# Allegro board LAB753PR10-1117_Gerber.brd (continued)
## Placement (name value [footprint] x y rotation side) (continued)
PR208  0_0402_5%  [R_0402]  150.92 24.98 90 top
PR209  0_0402_5%  [R_0402]  148.25 24.99 90 top
PR210  100K_0402_5%  [R_0402]  152.71 24.98 90 top
PR300  0_0402_5%  [R_0402]  239.88 26.25 0 bottom
PR301  100K_0402_5%  [R_0402]  243.02 24.86 180 bottom
PR302  2.2_0603_5%  [R_0603]  245.87 24.73 0 bottom
PR303  137K_0402_1%  [R_0402]  239.88 24.39 0 bottom
PR304  0_0402_5%  [R_0402]  239.88 25.36 0 bottom
PR305  4.7_1206_5%  [R_1206]  256.99 24.86 90 bottom
PR306  470K_0402_1%  [R_0402]  242.39 30.06 180 bottom
PR307  5.23K_0402_1%  [R_0402]  240.79 29.05 180 bottom
PR308  10K_0402_1%  [R_0402]  240.79 28.16 180 bottom
PR309  2.2_0603_5%  [R_0603]  133.94 106.91 0 bottom
PR310  10K_0402_1%  [R_0402]  130.34 110.94 180 bottom
PR311  470K_0402_1%  [R_0402]  131.76 112.49 90 bottom
PR312  137K_0402_1%  [R_0402]  129.43 107.22 0 bottom
PR313  20K_0402_1%  [R_0402]  129.4 109.06 0 bottom
PR314  4.7_1206_5%  [R_1206]  143.32 108.04 0 top
PR315  0_0402_5%  [R_0402]  129.4 108.17 0 bottom
PR316  9.31K_0402_1%  [R_0402]  129.44 111.86 90 bottom
PR317  0_0402_1%  [R_0402]  157.91 117.88 0 bottom
PR318  100K_0402_5%  [R_0402]  132.72 106.9 180 bottom
PR319  100_0402_1%  [R_0402]  130.35 112.78 270 bottom
PR403  1M_0402_1%  [R_0402]  142.83 85.1 180 bottom
PR405  4.99K_0402_1%  [R_0402]  204.97 23.87 270 top
PR406  5.62K_0402_1%  [R_0402]  203.68 22.47 270 top
PR407  12K_0402_1%  [R_0402]  204.79 18.07 270 top
PR500  130_0402_1%~D  [R_0402]  135.59 130.37 45 top
PR501  0_0402_5%  [R_0402]  102.68 119.46 90 top
PR502  2.2_0603_5%  [R_0603]  101.54 116.04 270 top
PR503  75_0402_5%  [R_0402]  136.1 132.41 315 bottom
PR504  54.9_0402_1%  [R_0402]  138.17 130.23 135 top
PR505  0_0402_5%  [R_0402]  135.6 131.66 225 top
PR506  0_0402_5%  [R_0402]  135.42 131.73 315 bottom
PR507  21K_0402_1%  [R_0402]  133.55 129.87 315 bottom
PR508  0_0402_5%  [R_0402]  138.18 131.52 315 top
PR509  3.24K_0402_1%  [R_0402]  134.17 130.49 315 bottom
PR510  10K_0603_1%  [R_0603]  141.23 119.99 225 top
PR511  0_0402_5%  [R_0402]  139.3 131.34 225 bottom
PR512  21K_0402_1%  [R_0402]  134.78 131.11 315 bottom
PR513  4.7_1206_5%  [R_1206]  110.37 120.99 0 top
PR514  3.65K_0603_1%  [R_0603]  140.38 120.84 225 top
PR515  10_0402_1%  [R_0402]  139.26 120 315 bottom
PR516  10K_0402_1%  [R_0402]  143.53 123.1 315 bottom
PR518  10K_0402_1%  [R_0402]  142.95 124.99 135 bottom
PR519  1.91K_0402_1%  [R_0402]  139.26 130.08 45 bottom
PR520  0_0402_5%  [R_0402]  132.02 124.68 225 bottom
PR521  90.9K_0402_1%  [R_0402]  140.57 129.11 45 top
PR522  0_0402_5%  [R_0402]  140.54 130.1 225 bottom
PR523  0_0402_5%~D  [R_0402]  132.46 123.78 45 bottom
PR524  0_0402_5%  [R_0402]  141.17 128.23 135 bottom
PR525  3.83K_0402_1%  [R_0402]  143.09 132.25 180 bottom
PR526  0_0402_5%  [R_0402]  136.15 120.05 225 bottom
PR527  0_0402_5%  [R_0402]  141.73 131.22 315 bottom
PR528  27.4K_0402_1%  [R_0402]  142.45 133.12 180 bottom
PR529  6.04K_0402_1%  [R_0402]  137.6 128.11 315 top
PR530  1_0603_1%~D  [R_0603]  136.31 118.49 315 bottom
PR533  499_0402_1%  [R_0402]  141.56 127.09 180 top
PR534  2.2_0603_5%  [R_0603]  132.1 129.66 315 bottom
PR535  590_0402_1%  [R_0402]  139.89 121.87 315 bottom
PR536  3.65K_0603_1%  [R_0603]  144.46 123.32 0 top
PR537  2.87K_0402_1%  [R_0402]  142.45 125.27 180 top
PR538  10K_0603_1%  [R_0603]  145.86 124.56 180 top
PR539  909_0402_1%  [R_0402]  146.34 124.32 90 bottom
PR541  4.7_1206_5%  [R_1206]  118.43 121.19 0 top
PR543  2K_0402_1%  [R_0402]  139.12 126.32 315 top
PR544  10_0402_1%  [R_0402]  143.58 124.35 225 bottom
PR545  1.5K_0402_1%  [R_0402]  139.93 120.59 135 bottom
PR546  10K_0402_1%  [R_0402]  144.79 123.07 135 bottom
PR547  10K_0402_1%  [R_0402]  141.15 119.35 135 bottom
PR548  0_0402_5%  [R_0402]  142.36 121.76 315 bottom
PR549  11K_0402_1%  [R_0402]  137.22 124.35 315 top
PR550  2.2_0603_5%  [R_0603]  134.07 121.22 45 bottom
PR551  2.61K_0402_1%  [R_0402]  140.66 121.88 135 top
PR552  3.65K_0603_1%  [R_0603]  143.39 123.92 270 top
PR553  10K_0603_1%  [R_0603]  142.31 123.66 180 top
PR554  4.7_1206_5%  [R_1206]  127.51 120.61 0 top
PR555  10K_0402_1%  [R_0402]  144.81 124.31 135 bottom
PR556  10_0402_1%  [R_0402]  142.98 122.41 135 bottom
PR557  10K_0402_1%  [R_0402]  141.76 120 135 bottom
PR558  5.1M_0402_5%  [R_0402]  138.08 119.98 135 bottom
PR600  0_0402_5%~D  [R_0402]  174.84 24.47 270 top
PR601  2.2 +-5% 0603  [R_0603]  177.71 29.78 90 top
PR602  0_0402_5%~D  [R_0402]  175.71 23.57 0 top
PR603  0.005_1206_LE_1%  [PS0612FKM070R005Z_1206-LE]  157.58 47.99 180 top
PR604  0.005_1206_LE_1%  [PS0612FKM070R005Z_1206-LE]  169.04 43.18 90 top
PR606  39.2K_0402_1%  [R_0402]  180.28 21.95 270 top
PR607  0_0402_5%  [R_0402]  176.52 26.33 180 top
PR608  4.7_1206_5%  [R_1206]  175.32 45.09 0 top
PR610  0_0402_5%  [R_0402]  176.52 25.44 180 top
PR611  1.5K_0402_1%  [R_0402]  177.55 21.95 270 top
PR613  39.2K_0402_1%  [R_0402]  179.36 21.03 90 top
PR614  10K_0402_1%~D  [R_0402]  175.62 29.21 0 top
PR615  0_0402_5%  [R_0402]  176.53 28.32 180 top
PR616  30.1K_0402_1%  [R_0402]  174.78 21.71 0 top
PR617  2.2 +-5% 0603  [R_0603]  184.82 29.78 90 top
PR618  1.5K_0402_1%  [R_0402]  174.78 22.67 0 top
PR619  0_0402_5%  [R_0402]  184.63 26.26 0 top
PR620  0_0402_5%~D  [R_0402]  182.58 19.05 180 top
PR621  0_0402_5%  [R_0402]  176.53 30.19 180 top
PR622  0_0402_5%  [R_0402]  186.36 20.8 180 top
PR623  3K_0402_1%  [R_0402]  177.52 20.12 0 top
PR624  100_0402_1%  [R_0402]  183 21.03 90 top
PR625  2.2 +-5% 0603  [R_0603]  182.37 29.86 90 top
PR626  4.7_1206_5%  [R_1206]  183.53 45.09 0 top
PR627  0_0402_5%  [R_0402]  186.36 21.71 180 top
PR629  100_0402_1%  [R_0402]  185.54 22.6 180 top
PR631  10K_0402_1%~D  [R_0402]  181.66 18.15 0 top
PR633  2.2 +-5% 0603  [R_0603]  188.34 27.33 180 top
PR638  10K_0402_1%  [R_0402]  185.54 23.59 180 top
PR639  10K_0402_1%~D  [R_0402]  185.55 27.15 180 top
PR640  4.7_1206_5%  [R_1206]  190.69 45.03 0 top
PR641  0_0402_5%  [R_0402]  188.76 31.3 180 top
PR642  0_0402_5%  [R_0402]  190.5 27.71 0 top
PR643  2.2 +-5% 0603  [R_0603]  193.8 31.46 180 top
PR646  10K_0402_1%  [R_0402]  185.54 24.47 180 top
PR648  10K_0402_1%  [R_0402]  185.54 25.36 180 top
PR649  10K_0402_1%  [R_0402]  180.03 31.21 270 top
PR650  510K_0402_1%  [R_0402]  182.06 21.95 270 top
PR674  4.7_1206_5%  [R_1206]  145.05 88.27 270 bottom
PR677  200K_0402_5%  [R_0402]  141.91 84.15 0 bottom
PR681  30.1K_0402_1%  [R_0402]  140.36 85.1 180 bottom
PR685  38.3K_0402_1%  [R_0402]  139.45 86.03 0 bottom
PR700  1M_0402_5%  [R_0402]  32.88 39.66 180 top
PR701  3M_0402_5%  [R_0402]  31.98 40.6 0 top
PR702  0.004_1206_1%  [R_1206_4P-D]  45 22.95 0 top
PR703  0_0402_5%  [R_0402]  41.47 29.67 90 top
PR704  0_0402_5%  [R_0402]  42.36 29.67 90 top
PR705  4.12K_0603_1%  [R_0603]  35.16 39.31 0 top
PR706  4.12K_0603_1%  [R_0603]  35.15 40.6 0 top
PR707  10_1206_1%  [R_1206]  35.5 37.87 270 top
PR708  2.2_0603_1%  [R_0603]  43.36 42.94 270 top
PR709  20K_0402_1%  [R_0402]  46.23 39.09 0 top
PR710  6.65K_0402_1%  [R_0402]  48.05 39.1 90 top
PR711  2.7K_0402_1%  [R_0402]  46.23 39.99 0 top
PR712  0.01_1206_1%  [R_1206_4P-D]  62.71 45.94 0 bottom
PR713  4.7_1206_5%  [R_1206]  51.69 41.94 270 top
PR714  100K_0402_5%  [R_0402]  37.49 38.21 0 top
PR715  120K_0402_5%  [R_0402]  38.4 37.32 180 top
PR716  324K_0402_1%  [R_0402]  37.49 36.45 0 top
PR717  0_0402_5%  [R_0402]  39.36 34.89 270 top
PR718  10K_0402_5%  [R_0402]  46.33 35.7 0 top
PR719  49.9K_0402_1%  [R_0402]  37.51 35.59 270 top
PR720  0_0402_5%  [R_0402]  43.1 32.87 90 top
PR721  0_0402_5%  [R_0402]  43.99 32.88 90 top
PR722  10_0402_5%  [R_0402]  47.61 38.15 0 top
PR723  10_0402_5%  [R_0402]  47.61 37.26 0 top
PR724  0_0402_5%  [R_0402]  42.21 32.87 90 top
PR725  4.7_0402_5%  [R_0402]  38.81 17.2 180 bottom
PR726  4.7_0402_5%  [R_0402]  38.81 16.31 180 bottom
PR727  0_0402_5%  [R_0402]  47.25 34.76 180 top
PR729  1M_0402_1%  [R_0402]  65.13 49 0 top
PR730  1M_0402_1%  [R_0402]  66.04 49.98 180 top
PR731  200K_0402_1%  [R_0402]  59.73 49.16 90 top
PR732  3.3K_0402_1%  [R_0402]  59.73 48.19 0 top
PU100  -  [TPS51285BRUKR_QFN20_3X3]  21.95 29.83 270 top
PU200  -  [RT8207MZQW_WQFN20_3X3]  149.34 29.78 270 top
PU300  -  [TPS51212DSCR_SON10_3X3]  242.51 26.51 90 bottom
PU301  -  [TPS51212DSCR_SON10_3X3]  131.97 108.87 90 bottom
PU401  -  [RT9041E-15GQW_WDFN8_2X2]  206.3 21.68 180 top
PU500  ISL95812HRZ-T_QFN32_4x4  [ISL95812HRZ-T_QFN32_4X4]  137.9 128.85 315 bottom
PU501  -  [ISL6208BCRZ-T_QFN8_2X2]  102.88 115.96 0 top
PU600  -  [RT8813AGQW_WQFN24_4X4]  178.77 27.3 270 top
PU601  RT9610BZQW WDFN8 MOSFET DRIVER ET88  [ISL6208BCRZ-T_QFN8_2X2]  188.96 30.18 270 top
PU602  SY8036LDBC_DFN10_3X3  [SY8036DBC_DFN10_3X3]  143.03 89.55 270 bottom
PU700  -  [BQ24780RUYR_WQFN28_4X4]  40.82 38.59 0 top
Q28  -  [DMN66D0LDW-7_SOT363-6]  139.72 15.38 180 top
Q29  -  [DMN66D0LDW-7_SOT363-6]  142.83 11.58 180 top
Q30  -  [DMN66D0LDW-7_SOT363-6]  136.35 15.38 180 top
Q31  -  [DMN66D0LDW-7_SOT363-6]  138.45 11.58 180 top
Q32  -  [DMN66D0LDW-7_SOT363-6]  132.99 15.43 180 top
Q33  -  [DMN66D0LDW-7_SOT363-6]  124.99 11.45 180 top
Q34  -  [DMN66D0LDW-7_SOT363-6]  129.62 15.26 180 top
Q35  -  [DMN66D0LDW-7_SOT363-6]  121.62 11.45 180 top
Q36  -  [DMN66D0LDW-7_SOT363-6]  126.26 15.26 180 top
Q37  -  [DMN66D0LDW-7_SOT363-6]  118.25 11.45 180 top
Q38  -  [DMN66D0LDW-7_SOT363-6]  122.89 15.26 180 top
Q39  -  [DMN66D0LDW-7_SOT363-6]  114.89 11.45 180 top
Q40  -  [2N7002K_SOT23-3]  311.49 39.84 90 top
Q41  -  [2N7002K_SOT23-3]  144.44 24.69 270 top
Q2407  -  [MMST3904-7-F_SOT323-3]  132.69 116.64 90 top
Q2408  -  [MMST3904-7-F_SOT323-3]  202.35 52.39 315 bottom
Q2409  SI3456DDV-T1-GE3_TSOP6~D  [SI3456DDV-T1-GE3_TSOP6]  213.42 123.14 180 bottom
Q2410  SSM3K7002FU_SC70-3~D  [SSM3K7002FU_SC70-3]  213.28 121.01 90 bottom
Q2411  -  [DMN66D0LDW-7_SOT363-6]  89.08 12.41 0 top
Q2412  -  [DMN66D0LDW-7_SOT363-6]  79.81 12.41 0 top
Q2413  -  [DMN66D0LDW-7_SOT363-6]  82.22 12.41 0 top
QA2  SSM3K7002FU_SC70-3~D  [SSM3K7002FU_SC70-3]  14.2 14.07 270 bottom
QA3  -  [SSM3K7002FU_SC70-3]  14.2 16.5 270 bottom
QA7  -  [DMN66D0LDW-7_SOT363-6]  4.57 7.82 90 top
QA11  -  [AO3413_SOT23-3]  27.07 9.46 0 bottom
QA12  -  [AO3413_SOT23-3]  17.74 11.41 90 bottom
QA13  -  [AO3413_SOT23-3]  23.1 8.93 0 bottom
QA14  -  [DMN66D0LDW-7_SOT363-6]  9.69 15.36 0 bottom
QC1  LBSS138LT1G_SOT-23-3  [LBSS138LT1G_SOT23-3]  120.87 109.88 90 top
QE1  SSM3K7002F_SC59-3~D  [SSM3K7002F_SC59-3]  262.69 20.11 135 bottom
QE3  SSM3K7002F_SC59-3~D  [SSM3K7002F_SC59-3]  276.08 19.99 225 bottom
QE4  SSM3K7002F_SC59-3~D  [SSM3K7002F_SC59-3]  268.71 19.29 225 bottom
QE6  SSM3K7002F_SC59-3~D  [SSM3K7002F_SC59-3]  273.35 17.32 225 bottom
QE7  SSM3K7002F_SC59-3~D  [SSM3K7002F_SC59-3]  266.97 17.71 135 bottom
QE8  LP2301ALT1G 1P SOT-23-3  [SI2301CDS-T1-GE3_SOT23-3]  283.3 7.96 270 bottom
QE9  -  [SSM3K7002F_SC59-3]  287.9 8.22 90 bottom
QE10  -  [SSM3K7002F_SC59-3]  172.2 134.56 270 bottom
QE12  DMN66D0LDW-7_SOT363-6~D  [DMN66D0LDW-7_SOT363-6]  166.94 136.39 270 bottom
QE13  DMN66D0LDW-7_SOT363-6~D  [DMN66D0LDW-7_SOT363-6]  163.2 137.49 90 bottom
QE14  SSM3K7002F_SC59-3~D  [SSM3K7002F_SC59-3]  156.76 130.12 180 top
QE16  -  [DMN66D0LDW-7_SOT363-6]  224.04 111.57 90 top
QF2  -  [MMBT3904WT1G_SC70-3]  217.17 123 0 bottom
QH1  SSM3K7002FU_SC70-3~D  [SSM3K7002FU_SC70-3]  234.25 35.47 90 bottom
QH3  DMN66D0LDW-7  [DMN66D0LDW-7_SOT363-6]  231.09 20.66 180 top
QH4  -  [DMN66D0LDW-7_SOT363-6]  225.92 18.79 0 top
QL3  2N7002_SOT23  [2N7002_SOT23-3]  321.25 71.81 180 top
QM1  LP2301ALT1G 1P SOT-23-3  [SI2301CDS-T1-GE3_SOT23-3]  291.91 32.15 0 top
QM2  -  [DMN66D0LDW-7_SOT363-6]  294.22 27.46 90 top
QM3  LP2301ALT1G 1P SOT-23-3  [SI2301CDS-T1-GE3_SOT23-3]  296.17 32.13 0 top
QN2  DII-DMN65D8LW-7~D  [SSM3K7002FU_SC70-3]  174.44 18.95 270 top
QN3  SSM3K7002FU_SC70-3~D  [SSM3K7002FU_SC70-3]  151.41 15.13 180 bottom
QN4  -  [2N7002K_SOT23-3]  165.62 33.36 270 top
QN5  -  [2N7002K_SOT23-3]  165.62 29.32 270 top
QV1  -  [SI3457CDV-T1-GE3_TSOP6]  82.9 117.24 315 top
QV2  -  [2N7002KW_SOT323-3]  81.69 113.4 180 top
QV12  2N7002H 1N_SOT23-3  [2N7002_SOT23-3]  140.92 77.54 90 bottom
QV13  2N7002DW-T/R7_SOT363-6  [2N7002DW-T-R7_SOT363-6]  162.75 53.2 270 top
QV21  2N7002W-T/R7_SOT323-3  [2N7002W-T-R7_SOT323-3]  213.3 104 180 bottom
QV23  2N7002W-T/R7_SOT323-3  [2N7002W-T-R7_SOT323-3]  157.04 128.04 270 top
QV24  2N7002W-T/R7_SOT323-3  [2N7002W-T-R7_SOT323-3]  198.88 132.67 270 top
QV25  2N7002W-T/R7_SOT323-3  [2N7002W-T-R7_SOT323-3]  215.08 65.41 0 bottom
QV89  2N7002DW-T/R7_SOT363-6  [2N7002DW-T-R7_SOT363-6]  159.75 53.81 0 bottom
QV91  2N7002DW-T/R7_SOT363-6  [2N7002DW-T-R7_SOT363-6]  149.63 57.89 0 top
R1  0_0402_5%  [R0402_0OHM]  92.65 64.87 270 top
R2  56_0402_5%  [R_0402]  87.94 101.88 0 bottom
R3  100_0402_1%  [R_0402]  91.44 108.75 270 top
R144  39K_0402_5%  [R_0402]  137.42 14.43 90 top
R145  39K_0402_5%  [R_0402]  127.32 14.43 90 top
R146  100K_0402_5%  [R_0402]  137.42 13.57 270 top
R147  100K_0402_5%  [R_0402]  127.32 13.57 270 top
R148  100K_0402_5%  [R_0402]  87.05 13.81 0 top
R149  39K_0402_5%  [R_0402]  87.05 12.92 0 top
R150  39K_0402_5%  [R_0402]  140.46 10.87 90 top
R151  39K_0402_5%  [R_0402]  119.32 10.87 90 top
R152  100K_0402_5%  [R_0402]  77.84 13.74 0 top
R153  39K_0402_5%  [R_0402]  77.84 12.85 0 top
R154  100K_0402_5%  [R_0402]  140.46 10.01 270 top
R155  100K_0402_5%  [R_0402]  119.32 10.01 270 top
R156  39K_0402_5%  [R_0402]  130.69 14.43 90 top
R157  39K_0402_5%  [R_0402]  123.95 14.43 90 top
R158  100K_0402_5%  [R_0402]  134.01 13.59 270 top
R159  100K_0402_5%  [R_0402]  123.95 13.57 270 top
R160  39K_0402_5%  [R_0402]  139.51 10.87 90 top
R161  39K_0402_5%  [R_0402]  115.95 10.87 90 top
R162  100K_0402_5%  [R_0402]  139.51 10.01 270 top
R163  100K_0402_5%  [R_0402]  115.95 10.01 270 top
R164  39K_0402_5%  [R_0402]  134.03 14.48 90 top
R165  39K_0402_5%  [R_0402]  120.59 14.43 90 top
R166  100K_0402_5%  [R_0402]  130.69 13.57 270 top
R167  100K_0402_5%  [R_0402]  120.59 13.57 270 top
R168  39K_0402_5%  [R_0402]  122.68 10.87 90 top
R169  39K_0402_5%  [R_0402]  112.59 10.75 90 top
R170  100K_0402_5%  [R_0402]  122.68 10.01 270 top
R171  100K_0402_5%  [R_0402]  112.59 9.88 270 top
R172  100K_0402_5%  [R_0402]  85.42 13.81 180 top
R173  39K_0402_5%  [R_0402]  85.42 12.92 180 top
R174  10K_0402_5%  [R_0402]  50.08 15.74 270 bottom
R175  100K_0402_5%  [R_0402]  313.25 39.38 90 top
R176  100K_0402_5%  [R_0402]  307.6 40.3 270 top
R177  22_0603_5%  [R_0603]  142.24 23.08 0 top
R178  0_0402_5%  [R0402_0OHM]  229.07 21.22 90 bottom
R179  300K_0402_5%~D  [R_0402]  212.17 119.92 180 bottom
R180  1.5M_0402_5%~D  [R_0402]  212.17 120.82 180 bottom
R181  10K_0402_5%  [R_0402]  140.46 10.58 90 bottom
R182  0_0402_5%  [R0402_0OHM]  50.98 15.74 270 bottom
RA40  33_0402_5%~D  [R_0402]  20.16 21.76 270 top
RA41  10K_0402_5%  [R_0402]  3.81 15.6 0 bottom
RA42  20K_0402_1%~D  [R_0402]  18.46 7.58 90 top
RA43  10K_0402_5%~D  [R_0402]  14.54 13.18 270 bottom
RA44  10K_0402_5%~D  [R_0402]  4.73 13.77 90 bottom
RA46  39.2K_0402_1%  [R_0402]  24.35 10.68 0 top
RA47  20K_0402_1%~D  [R_0402]  26.04 12.49 180 top
RA48  10K_0402_1%~D  [R_0402]  24.35 11.58 0 top
RA49  5.11K_0402_1%~D  [R_0402]  26.04 13.38 180 top
RA50  0_0402_5%~D  [R_0402]  6.05 12.24 90 bottom
RA51  0_0402_5%  [R0402_0OHM]  21.5 22.65 270 top
RA53  0_0402_5%~D  [R_0402]  10.42 33.75 225 bottom
RA54  0_0402_5%~D  [R_0402]  1.65 16.32 90 bottom
RA55  0_0805_5%~D  [R_0805]  13.73 20.02 270 bottom
RA57  0_0805_5%~D  [R_0805]  17.63 14.23 180 bottom
RA64  10K_0402_1%~D  [R_0402]  19.34 7.58 90 top
RA80  10K_0402_5%~D  [R_0402]  223.98 16.09 180 bottom
RA81  560_0402_5%  [R_0402]  225.74 15.19 90 bottom
RA84  560_0402_5%  [R_0402]  224.86 15.19 90 bottom
RA85  100K_0402_1%  [R_0402]  8.68 16.8 180 bottom
RA86  100K_0402_1%  [R_0402]  5.96 15.84 0 bottom
RA87  100K_0402_1%  [R_0402]  5.96 16.73 0 bottom
RA91  100K_0402_1%  [R_0402]  7.98 33.92 0 bottom
RA92  0_0402_5%  [R0402_0OHM]  17.97 7.81 90 bottom
RA93  0_0402_5%~D  [R_0402]  6.65 8.27 180 top
RA94  0_0402_5%~D  [R_0402]  6.63 9.18 180 top
RA95  0_0603_5%  [R0603_0OHM]  27.07 11.47 0 bottom
RA96  0_0402_5%  [R_0402]  24.01 20.11 90 top
RA100  2.2K_0402_5%  [R_0402]  16.04 11 270 bottom
RA101  10K_0804_8P4R_5%~D  [RP_0804_8P4R]  22.45 6.16 180 top
RA102  2.2K_0402_5%  [R_0402]  28.41 8.69 270 top
RA105  24.9K_0402_1%  [R_0402]  14.99 8.27 90 bottom
RA106  24.9K_0402_1%  [R_0402]  29.48 9.37 270 bottom
RA107  100_0402_1%  [R_0402]  6.54 8.87 270 bottom
RA108  100_0402_1%  [R_0402]  14.1 8.27 90 bottom
RA109  10_0603_5%  [R_0603]  10 20.77 270 bottom
RA111  5.6K_0402_1%  [R_0402]  8.89 34.86 180 bottom
RA112  10K_0402_1%  [R_0402]  6.02 33.92 0 bottom
RA113  10K_0402_1%  [R_0402]  6.85 32.66 225 bottom
RA114  10K_0402_1%  [R_0402]  8.66 12.5 0 bottom
RA115  10K_0402_1%  [R_0402]  8.65 14.86 270 bottom
RA116  5.9K_0402_5%  [R_0402]  5.09 33.77 180 bottom
RA117  5.9K_0402_5%  [R_0402]  9.97 31.65 270 bottom
RA118  13.3K_0402_1%  [R_0402]  12.7 8.21 90 top
RA119  13.3K_0402_1%  [R_0402]  9.39 6.5 180 top
RA120  10K_0402_1%  [R_0402]  14.49 8.22 180 top
RA122  10K_0402_1%  [R_0402]  6.64 6.5 0 top
RA123  470K_0402_5%  [R_0402]  5.78 6.54 180 top
RA126  2.2K_0402_5%  [R_0402]  2.62 12.28 180 bottom
RA127  5.1K_0402_1%  [R_0402]  24.56 16.23 180 bottom
RA128  12K_0402_1%  [R_0402]  28.12 16.35 0 bottom
RA129  10K_0402_5%  [R_0402]  25.48 17.13 180 bottom
RA130  10_0402_1%  [R_0402]  4.66 16.47 90 bottom
RA131  10_0402_1%  [R_0402]  3.71 16.47 90 bottom
RA132  10_0402_1%  [R_0402]  1.72 18.2 90 bottom
RA133  10_0402_1%  [R_0402]  2.59 18.2 90 bottom
RA137  66.5K_0402_1%  [R_0402]  6.05 14.92 270 bottom
RA138  10K_0402_1%  [R_0402]  4.22 6.23 180 bottom
RA139  100K_0402_5%  [R_0402]  4.13 31.88 270 bottom
RA140  100K_0402_5%  [R_0402]  9.89 29.32 225 bottom
RC1  24.9_0402_1%  [R_0402]  132.79 83.84 180 top
RC11  62_0402_5%  [R_0402]  88.85 102.77 180 bottom
RC12  470_0402_5%  [R_0402]  92.65 63.1 270 top
RC17  0_0402_5%  [R0402_0OHM]  88.85 100.29 180 bottom
RC18  10K_0402_5%  [R_0402]  89.46 96.8 0 top
RC21  100_0402_1%  [R_0402]  96.71 64.87 270 top
RC22  75_0402_1%  [R_0402]  94.43 64.87 270 top
RC23  100_0402_1%  [R_0402]  95.57 64.87 270 top
RC24  100K_0402_5%  [R_0402]  82.67 64.92 0 top
RC26  1.8K_0402_1%  [R_0402]  89.85 62.18 90 top
RC27  1K_0402_5%  [R_0402]  87.94 99.4 0 bottom
RC30  3.3K_0402_1%  [R_0402]  90.74 63.1 270 top
RC31  0_0402_5%  [R0402_0OHM]  88.66 63.58 270 top
RC32  24.9_0402_1%  [R_0402]  123.26 83.13 90 top
RC33  0_0402_5%  [R_0402]  122.75 108.34 90 top
RC34  10K_0402_5%  [R_0402]  122.75 110.18 90 top
RC35  100K_0402_5%  [R_0402]  117.05 109.6 270 top
RC36  1K_0402_1%  [R_0402]  91.26 85.24 180 top
RC37  1K_0402_1%  [R_0402]  90.35 87.91 0 top
RC38  49.9_0402_1%  [R_0402]  114.37 109.32 270 top
RC39  49.9_0402_1%  [R_0402]  90.29 92.8 0 top
RC40  49.9_0402_1%  [R_0402]  113.48 109.32 270 top
RC41  1K_0402_1%  [R_0402]  91.26 90.2 180 top
RC42  1K_0402_1%  [R_0402]  91.26 86.96 180 top
RC43  1K_0402_1%  [R_0402]  91.26 89.27 180 top
RC44  100_0402_1%  [R_0402]  94.11 107.83 90 top
RC45  0_0402_5%  [R0402_0OHM]  93.22 107.83 90 top
RC46  0_0402_5%  [R0402_0OHM]  92.33 107.83 90 top
RC47  75_0402_1%  [R_0402]  89.28 107.83 90 top
RC48  43_0402_5%  [R_0402]  88.39 108.75 270 top
RC49  130_0402_1%  [R_0402]  90.36 108.75 270 top
RC50  150_0402_1%  [R_0402]  116.14 108.41 90 top
RC51  0_0603_5%  [R_0603]  88.97 105.19 180 bottom
RC52  10K_0402_5%  [R_0402]  115.25 109.32 270 top
RC53  6.04K_0402_1%  [R_0402]  133.42 95.88 90 top
RC54  0_0603_5%  [R_0603]  123.89 108.36 90 top
RC55  2.67K_0402_1%  [R_0402]  132.47 96.8 270 top
RC56  0_0402_5%  [R_0402]  80.79 63.02 0 top
RC57  0_0402_5%  [R_0402]  80.8 64.92 0 top
RD1  1K_0402_1%  [R_0402]  121.87 45.37 180 bottom
RD2  2.2_0402_1%  [R_0402]  126.05 46.27 270 bottom
RD3  1K_0402_1%  [R_0402]  123.89 46.27 270 bottom
RD4  24.9_0402_1%  [R_0402]  124.97 48.68 270 bottom
RD5  1K_0402_1%  [R_0402]  84.77 43.7 90 bottom
RD6  2.2_0402_1%  [R_0402]  80.75 43.7 90 bottom
RD7  10K_0402_5%  [R_0402]  136.78 44.55 270 bottom
RD8  10K_0402_5%  [R_0402]  139.83 44.62 270 bottom
RD9  1K_0402_1%  [R_0402]  81.64 43.7 90 bottom
RD10  24.9_0402_1%  [R_0402]  81.64 41.86 90 bottom
RD11  1K_0402_1%  [R_0402]  76.44 24.41 0 top
RD12  2.2_0402_1%  [R_0402]  73.87 22.49 0 top
RD13  1K_0402_1%  [R_0402]  73.87 23.45 0 top
RD14  24.9_0402_1%  [R_0402]  74.78 20.58 180 top
RD15  10K_0402_5%  [R_0402]  141.47 27.78 0 top
RD16  10K_0402_5%  [R_0402]  140.74 25.08 90 top
RE1  4.7K_0402_5%  [R_0402]  259.37 22.62 45 bottom
RE2  4.7K_0402_5%  [R_0402]  260.04 21.94 45 bottom
RE3  0_0603_5%  [R0603_0OHM]  259.27 31.78 90 bottom
RE4  0_0603_5%  [R0603_0OHM]  265.38 38.49 315 bottom
RE5  0_0603_5%~D  [R_0603]  268.73 36.73 180 bottom
RE6  0_0603_5%  [R0603_0OHM]  255.89 38.66 270 top
RE7  1K_0402_1%~D  [R_0402]  268.99 34.49 225 bottom
RE8  10K_0402_5%  [R_0402]  272.39 20.69 135 bottom
RE9  15_0402_5%  [R_0402]  252.03 40.36 270 bottom
RE10  15_0402_5%  [R_0402]  256.15 31.52 0 bottom
RE11  15_0402_5%  [R_0402]  254.55 41.94 180 bottom
RE12  10K_0402_5%~D  [R_0402]  259.12 35.59 270 bottom
RE13  10K_0402_5%~D  [R_0402]  259.98 39.02 180 bottom
RE14  10K_0402_5%~D  [R_0402]  259.98 38.06 180 bottom
RE15  100K_0402_5%  [R_0402]  263.59 17.95 45 bottom
RE16  100K_0402_5%  [R_0402]  273.11 20.04 315 bottom
RE17  100K_0402_5%  [R_0402]  271.38 19.68 135 bottom
RE18  0_0603_5%  [R_0603]  261.96 37.4 0 top
RE19  0_0402_5%~D  [R_0402]  266.65 27.41 0 top
RE20  10K_0402_5%  [R_0402]  252.4 44.73 0 top
RE21  100K_0402_5%  [R_0402]  272.61 18.19 225 bottom
RE23  100K_0402_5%  [R_0402]  267.86 15.55 45 bottom
RE25  4.7K_0402_1%  [R_0402]  219.89 111.19 180 top
RE26  4.7K_0402_1%~D  [R_0402]  153.93 21.95 270 top
RE27  4.7K_0402_1%  [R_0402]  153.91 20.16 0 top
RE28  100K_0402_5%  [R_0402]  279.34 8.23 270 bottom
RE29  4.7K_0402_1%~D  [R_0402]  152.15 22.49 90 top
RE30  4.7K_0402_1%  [R_0402]  151.26 22.49 90 top
RE31  10K_0402_5%~D  [R_0402]  222.3 117.02 0 top
RE32  4.7K_0402_1%  [R_0402]  152.67 14.51 180 top
RE33  4.7K_0402_1%  [R_0402]  183.5 135.26 0 bottom
RE34  4.7K_0402_1%  [R_0402]  183.5 134.37 0 bottom
RE35  4.7K_0402_1%  [R_0402]  183.14 132.97 180 bottom
RE36  4.7K_0402_1%  [R_0402]  180.46 132.96 0 bottom
RE37  10K_0402_5%  [R_0402]  153.91 19.27 0 top
RE38  100K_0402_5%  [R_0402]  159.04 134.89 180 top
RE39  100K_0402_5%  [R_0402]  161.3 138.74 0 bottom
RE40  4.7K_0402_1%~D  [R_0402]  223.22 118.85 180 top
RE41  10K_0402_5%~D  [R_0402]  183.5 136.18 0 bottom
RE42  4.7K_0402_1%~D  [R_0402]  222.3 119.79 0 top
RE43  4.7K_0402_1%~D  [R_0402]  223.22 117.96 180 top
RE44  4.7K_0402_1%~D  [R_0402]  222.3 120.68 0 top
RE45  4.7K_0402_1%  [R_0402]  183.68 139.37 90 bottom
RE46  4.7K_0402_1%  [R_0402]  225.06 112.36 270 top
RE47  4.7K_0402_1%  [R_0402]  220.84 111.01 90 top
RE62  0_0402_5%  [R0402_0OHM]  215.53 12.14 180 top
RE63  100K_0402_5%  [R_0402]  158.87 139.4 0 top
RE64  100K_0402_1%  [R_0402]  273.5 9.76 270 top
RE66  27K_0402_1%  [R_0402]  274.45 8.84 90 top
RE68  47K_0402_5%  [R_0402]  270.79 25.24 0 top
RE70  10K_0402_5%  [R_0402]  289.24 9.63 270 top
RE72  10K_0402_5%  [R_0402]  296.05 25.49 180 top
RE74  43_0402_1%  [R_0402]  293.63 19.17 180 top
RE75  10K_0402_5%  [R_0402]  276.99 29.54 90 top
RE76  43_0402_1%  [R_0402]  292.71 21.77 0 top
RE77  10K_0402_5%  [R_0402]  279.36 7.83 90 top
RE78  0_0402_5%  [R0402_0OHM]  296.01 21.77 0 top
RE79  10K_0402_5%  [R_0402]  293.19 10.56 90 top
RE80  10K_0402_5%  [R_0402]  276.99 14.63 180 bottom
RE81  1K_0402_5%  [R_0402]  292.25 13.96 270 top
RE82  100K_0402_5%  [R_0402]  295.01 15.09 90 top
RE83  10K_0402_5%  [R_0402]  289.5 29.86 90 top
RE85  53.6K_0402_5%  [R_0402]  296.9 13.06 90 top
RE89  0_0402_5%  [R_0402]  284.8 30.77 270 top
RE90  2.2K_0804_8P4R_5%  [RP_0804_8P4R]  282.01 9.18 270 top
RE91  47K_0402_5%  [R_0402]  239.99 40.46 90 top
RE92  10K_0402_5%  [R_0402]  288.47 29.85 90 top
RE93  4.7K_0402_5%  [R_0402]  282.07 30.39 270 top
RE94  4.7K_0402_5%  [R_0402]  281.18 30.39 270 top
RE98  0_0402_5%  [R_0402]  243.65 46.84 270 top
RE99  100K_0402_5%  [R_0402]  239.77 37.47 0 bottom
RE100  4.7K_0402_5%  [R_0402]  185.79 131.5 90 bottom
RE101  4.7K_0402_5%  [R_0402]  186.7 131.5 90 bottom
RE102  100K_0402_5%  [R_0402]  236.45 45.53 180 top
RF1  10K_0402_5%  [R_0402]  67.73 59.23 270 bottom
RF2  10K_0402_5%  [R_0402]  66.75 57.6 90 bottom
RF3  10K_0402_5%  [R_0402]  66.78 59.37 180 bottom
RF4  10K_0402_5%  [R_0402]  250.21 45.07 135 bottom
RF5  10K_0402_5%  [R_0402]  248.19 47.09 315 bottom
RF6  10K_0402_5%  [R_0402]  238.64 52.21 0 bottom
RH1  0_0402_5%  [R0402_0OHM]  236.32 28.96 90 top
RH2  0_0402_5%  [R_0402]  235.41 31.94 180 top
RH3  330K_0402_1%~D  [R_0402]  234.96 26.38 180 bottom
RH4  330K_0402_1%~D  [R_0402]  231.73 31.42 270 top
RH5  10K_0402_5%~D  [R_0402]  209.6 27.54 0 top
RH6  1K_0402_1%~D  [R_0402]  235.47 39.84 180 top
RH7  10K_0402_5%~D  [R_0402]  209.04 24.42 270 bottom
RH8  4.7K_0402_5%~D  [R_0402]  208.16 23.51 90 bottom
RH9  0_0402_5%  [R0402_0OHM]  230.35 23.66 0 top
RH10  10K_0402_5%~D  [R_0402]  210.89 24.42 270 bottom
RH11  10M_0402_5%~D  [R_0402]  230.35 24.53 0 top
RH12  1M_0402_5%~D  [R_0402]  234.96 27.33 180 bottom
RH13  20K_0402_5%~D  [R_0402]  234.96 28.53 180 bottom
RH14  100K_0402_5%~D  [R_0402]  236.74 33.44 0 bottom
RH15  20K_0402_5%~D  [R_0402]  234.96 29.76 180 bottom
RH16  1K_0402_1%~D  [R_0402]  235.47 40.73 180 top
RH17  0_0603_5%~D  [R_0603]  224.69 19.55 180 bottom
RH18  51_0402_1%~D  [R_0402]  224.49 24.42 270 bottom
RH19  210_0402_1%~D  [R_0402]  221.68 21.03 90 bottom
RH20  1M_0402_5%~D  [R_0402]  237.37 34.69 90 bottom
RH21  210_0402_1%~D  [R_0402]  220.72 21.03 90 bottom
RH22  0_0402_5%  [R0402_0OHM]  209.6 30.23 0 top
RH23  210_0402_1%~D  [R_0402]  222.63 21.03 90 bottom
RH24  0_0402_5%  [R0402_0OHM]  230.95 18.96 270 bottom
RH25  100_0402_1%~D  [R_0402]  222.63 24.4 270 bottom
RH26  100_0402_1%~D  [R_0402]  221.66 24.4 270 bottom
RH27  100_0402_1%~D  [R_0402]  223.53 23.48 90 bottom
RH28  7.5K_0402_1%~D  [R_0402]  210.52 29.33 180 top
RH29  33_0402_5%~D  [R_0402]  235.18 42.01 180 bottom
RH30  10K_0402_5%~D  [R_0402]  218.34 20.16 270 top
RH31  10K_0402_5%~D  [R_0402]  229.11 18.05 90 bottom
RH32  0_0402_5%  [R0402_0OHM]  213.98 26.58 0 top
RH33  8.2K_0402_5%~D  [R_0402]  209.6 32.09 0 top
RH34  0_0402_5%  [R_0402]  229.75 24.61 270 bottom
RH35  10K_0402_5%~D  [R_0402]  224.5 16.36 270 top
RH36  10K_0402_5%~D  [R_0402]  221.48 18.57 0 top
RH37  10K_0402_5%~D  [R_0402]  223.59 23.51 90 top
RH38  10K_0402_5%~D  [R_0402]  230 18.05 90 bottom
RH39  649_0402_1%~D  [R_0402]  224.8 47.5 180 top
RH40  0_0402_5%  [R0402_0OHM]  211.58 51.32 90 bottom
RH41  7.5K_0402_1%~D  [R_0402]  212.47 52.24 270 bottom
RH42  7.5K_0402_1%~D  [R_0402]  211.62 36.29 0 top
RH43  10K_0402_5%~D  [R_0402]  226.19 18.96 270 bottom
RH44  10K_0402_5%~D  [R_0402]  152.34 55.31 0 top
RH45  0_0402_5%  [R0402_0OHM]  234.95 25.25 270 top
RH46  0_0402_5%  [R_0402]  234.06 25.25 270 top
RH47  0_0402_5%  [R0402_0OHM]  213.82 23.51 90 top
RH48  0_0402_5%~D  [R_0402]  223.28 19.73 270 top
RH49  0_0402_5%  [R0402_0OHM]  215.65 21.03 90 top
RH50  0_0402_5%  [R0402_0OHM]  217.45 19.23 90 top
RH51  100K_0402_5%~D  [R_0402]  227.14 18.96 270 bottom
RH52  0_0402_5%  [R0402_0OHM]  231.6 23.7 90 bottom
RH53  0_0402_5%  [R0402_0OHM]  231.23 20.42 90 bottom
RH54  100K_0402_5%  [R_0402]  233.31 46.13 180 top
RH55  0_0402_5%  [R0402_0OHM]  229.97 21.22 90 bottom
RH56  0_0402_5%  [R0402_0OHM]  224.47 23.51 90 top
RH57  100K_0402_5%  [R_0402]  225.87 47.86 270 top
RH58  8.2K_0402_5%~D  [R_0402]  231.08 17.13 0 top
RH59  8.2K_0402_5%~D  [R_0402]  233.15 34.97 180 top
RH60  10K_0402_5%~D  [R_0402]  234.65 37.64 180 bottom
RH61  8.2K_0402_5%~D  [R_0402]  234.96 30.67 180 bottom
RH62  8.2K_0402_5%~D  [R_0402]  233.33 37.31 180 top
RH63  8.2K_0402_5%~D  [R_0402]  233.17 38.23 180 top
RH64  8.2K_0402_5%~D  [R_0402]  233.19 36.41 180 top
RH65  330K_0402_1%  [R_0402]  234.05 25.43 0 bottom
RH66  8.2K_0402_5%~D  [R_0402]  233.17 39.12 180 top
RH67  10K_0402_5%~D  [R_0402]  206.94 34.13 0 top
RH68  10K_0402_5%  [R_0402]  233.9 29.87 0 top
RH69  10K_0402_5%  [R_0402]  233 30.8 0 top
RH70  330K_0402_1%  [R_0402]  234.96 24.47 180 bottom
RH71  1K_0402_1%  [R_0402]  234.06 31.94 0 bottom
RH72  0_0402_5%  [R_0402]  227.87 21.87 270 bottom
RH73  10K_0402_5%~D  [R_0402]  223.59 21.03 90 bottom
RH74  10K_0402_5%  [R_0402]  214.77 24.42 270 top
RH75  10K_0402_5%~D  [R_0402]  219.76 21.95 270 bottom
RH76  10K_0402_5%  [R_0402]  222.63 24.42 270 top
RH77  10K_0402_5%~D  [R_0402]  219.76 23.48 90 bottom
RH78  10K_0402_5%~D  [R_0402]  226.7 16.74 270 top
RH79  10K_0402_5%~D  [R_0402]  228.06 51.03 0 bottom
RH80  10K_0402_5%~D  [R_0402]  225.49 21.03 90 bottom
RH81  10K_0402_5%~D  [R_0402]  224.54 21.03 90 bottom
RH82  10K_0402_5%~D  [R_0402]  220.72 23.48 90 bottom
RH83  10K_0402_5%~D  [R_0402]  225.44 24.42 270 bottom
RH84  1M_0402_5%  [R_0402]  217.6 50.45 0 bottom
RH85  10K_0402_5%  [R_0402]  215.7 24.42 270 top
RH87  22_0402_5%~D  [R_0402]  228.56 45.64 180 top
RH89  22_0402_5%~D  [R_0402]  228.65 47.4 0 top
RH91  0_0402_5%  [R0402_0OHM]  214.31 52.24 270 bottom
RH92  7.5K_0402_1%  [R_0402]  213.44 51.32 90 bottom
RH93  2.2K_0402_5%  [R_0402]  226.63 17.82 180 top
RH94  2.2K_0402_5%  [R_0402]  226.3 21.68 0 top
RH95  0_0402_5%  [R0402_0OHM]  224.23 18.81 90 top
RH96  0_0402_5%  [R0402_0OHM]  228.35 19.98 270 top
RH97  2.2K_0402_5%  [R_0402]  224.54 21.95 270 top
RH98  10K_0402_5%~D  [R_0402]  208.8 35.1 0 top
RH99  2.2K_0402_5%  [R_0402]  228.46 16.59 90 top
RH100  1K_0402_1%  [R_0402]  225.43 23.51 90 top
RH101  10K_0402_5%  [R_0402]  228.16 18.05 90 bottom
RH102  0_0402_5%  [R_0402]  229.29 15.39 0 top
RH103  8.2K_0402_1%  [R_0402]  209.68 51.32 90 bottom
RH104  15_0402_1%  [R_0402]  212.26 25.67 90 top
RH105  1K_0402_5%  [R_0402]  220.6 15.45 90 bottom
RH106  1K_0402_5%  [R_0402]  214.75 20.28 0 bottom
RH107  3.3K_0402_5%~D  [R_0402]  207.63 22.06 0 bottom
RH108  33_0402_5%~D  [R_0402]  211.7 23.51 90 top
RH109  22.6_0402_1%  [R_0402]  227.04 38.53 0 top
RH110  0_0402_5%  [R0402_0OHM]  211.6 42.42 90 top
RH111  7.5K_0402_1%  [R_0402]  210.72 43.33 270 top
RH112  10K_0402_5%~D  [R_0402]  207.85 35.97 180 top
RH113  10K_0402_5%~D  [R_0402]  209.6 34 0 top
RH114  10K_0402_5%~D  [R_0402]  209.6 28.44 0 top
RH115  10K_0402_5%~D  [R_0402]  234.81 28.93 180 top
RH117  10K_0402_5%  [R_0402]  210.52 26.65 180 top
RH118  10K_0402_5%~D  [R_0402]  209.6 31.14 0 top
RH119  10K_0402_5%~D  [R_0402]  213.74 23.51 90 bottom
RH120  10K_0402_5%~D  [R_0402]  233.15 33.95 180 top
RH121  10K_0402_5%~D  [R_0402]  226.95 20.78 90 bottom
RH122  10K_0402_5%~D  [R_0402]  208.17 28.41 180 bottom
RH123  10K_0402_5%  [R_0402]  218.51 23.92 270 top
RH124  390_0402_5%  [R_0402]  207.1 24.41 270 bottom
RH126  10K_0402_5%  [R_0402]  211.84 24.42 270 bottom
RH127  0_0402_5%  [R_0402]  225.45 15.45 90 top
RH130  10K_0402_5%~D  [R_0402]  212.85 23.51 90 bottom
RH131  10K_0402_5%~D  [R_0402]  238.08 31.33 180 bottom
RH132  10K_0402_5%~D  [R_0402]  212.05 22.06 180 bottom
RH133  10K_0402_5%~D  [R_0402]  239 31.33 270 bottom
RH134  10K_0402_5%~D  [R_0402]  209.6 33.05 0 top
RH135  10K_0402_5%~D  [R_0402]  206.94 35.08 0 top
RH136  1K_0402_1%~D  [R_0402]  210 24.42 270 bottom
RH137  200K_0402_5%  [R_0402]  215.67 23.51 90 bottom
RH138  10K_0402_5%~D  [R_0402]  209.41 22.06 0 bottom
RH139  10K_0402_5%~D  [R_0402]  215.67 22.07 270 bottom
RH140  5.11_0402_1%~D  [R_0402]  229.5 23.64 90 top
RH141  0_0402_5%  [R0402_0OHM]  235.02 33.95 180 top
RH142  0_0402_5%~D  [R_0402]  223.78 49.79 180 top
RH143  0_0805_5%~D  [R_0805]  238.91 35.46 180 top
RH144  0_0402_5%  [R0402_0OHM]  206.94 35.54 0 bottom
RH145  0_0402_5%~D  [R_0402]  235.02 35.5 180 top
RH146  0_0805_5%  [R0805_0OHM]  214.73 56.16 0 top
RH147  0_0805_5%  [R0805_0OHM]  218.61 56.16 0 top
RH148  0_0805_5%  [R0805_0OHM]  236.48 36.9 90 top
RH149  0_0805_5%  [R0805_0OHM]  232.73 40.13 90 top
RH150  0_0603_5%  [R0603_0OHM]  214.91 57.62 180 top
RH151  10K_0402_5%~D  [R_0402]  235.47 33.83 180 bottom
RH152  10K_0402_5%  [R_0402]  238.51 18.14 270 top
RH153  0_0402_5%  [R0402_0OHM]  215.55 48.21 180 top
RH154  10K_0402_5%~D  [R_0402]  236.4 32.22 0 bottom
RH155  10K_0402_5%~D  [R_0402]  208.17 29.3 180 bottom
RH156  10K_0402_5%~D  [R_0402]  231.99 16.25 180 top
RH157  10K_0402_5%~D  [R_0402]  214.76 23.51 90 bottom
RH158  10K_0402_5%~D  [R_0402]  213.58 20.7 90 bottom
RH161  10K_0402_5%  [R_0402]  211.38 26.58 270 top
RI1  0_0402_5%~D  [R_0402]  318 59.53 0 bottom
RI4  0_0402_5%~D  [R_0402]  318 60.54 0 bottom
RI5  0_0402_5%~D  [R_0402]  319.58 66.51 0 bottom
RI8  0_0402_5%~D  [R_0402]  319.58 65.5 0 bottom
RI11  0_0402_5%~D  [R_0402]  319.58 64.61 0 bottom
RI13  0_0402_5%~D  [R_0402]  319.58 63.59 0 bottom
RI56  0_0402_5%~D  [R_0402]  317.87 46 0 bottom
RI58  0_0402_5%~D  [R_0402]  317.87 47.02 0 bottom
RI59  0_0402_5%~D  [R_0402]  319.65 50.19 0 bottom
RI60  0_0402_5%~D  [R_0402]  319.65 51.21 0 bottom
RI61  0_0402_5%~D  [R_0402]  319.65 52.1 0 bottom
RI62  0_0402_5%~D  [R_0402]  319.65 53.11 0 bottom
RI63  0_0402_5%~D  [R_0402]  15.54 20.16 180 top
RI64  0_0402_5%~D  [R_0402]  15.54 21.3 180 top
RI65  0_0402_5%~D  [R_0402]  15.54 22.25 180 top
RI66  0_0402_5%~D  [R_0402]  15.54 23.4 180 top
RI67  0_0402_5%~D  [R_0402]  15.54 24.35 180 top
RI68  0_0402_5%~D  [R_0402]  15.54 25.49 180 top
RI69  0_0402_5%~D  [R_0402]  15.54 26.44 180 top
RI70  0_0402_5%~D  [R_0402]  15.54 27.59 180 top
RI71  0_0402_5%~D  [R_0402]  15.54 28.54 180 top
RI72  0_0402_5%~D  [R_0402]  15.54 29.68 180 top
RI73  0_0402_5%~D  [R_0402]  15.54 30.63 180 top
RI74  0_0402_5%~D  [R_0402]  15.54 31.78 180 top
RI75  0_0402_5%  [R_0402]  186.25 135.32 90 bottom
RI76  0_0402_5%  [R_0402]  185.36 135.32 90 bottom
RI77  0_0402_5%  [R_0402]  188.72 138.64 90 bottom
RI78  0_0402_5%  [R_0402]  187.84 138.64 90 bottom
RL1  4.7K_0402_5%~D  [R_0402]  315.2 25.86 90 top
RL2  30K_0402_5%  [R_0402]  316.17 25.86 90 top
RL3  2.37K_0402_1%~D  [R_0402]  323.14 31.33 0 top
RL4  5.1K_0402_1%~D  [R_0402]  312.8 30.63 0 top
RL5  10K_0402_5%  [R_0402]  328.09 31.46 0 top
RL8  330_0402_5%  [R_0402]  320.61 89.13 270 top
RL9  75_0402_1%~D  [R_0402]  335.47 86.91 270 top
RL10  75_0402_1%~D  [R_0402]  332.49 86.97 270 top
RL11  75_0402_1%~D  [R_0402]  329.44 86.91 270 top
RL12  75_0402_1%~D  [R_0402]  326.46 86.91 270 top
RL13  130_0402_1%~D  [R_0402]  323.79 76.43 270 top
RL14  1K_0402_1%~D  [R_0402]  322.9 76.43 270 top
RL15  130_0402_5%~D  [R_0402]  322.9 74.46 270 top
RM5  10K_0402_5%  [R_0402]  191.68 139.22 90 bottom
RM6  10K_0402_5%  [R_0402]  197.32 138.06 90 bottom
RM14  1K_0402_1%  [R_0402]  150.28 136.81 90 bottom
RM17  100K_0402_5%  [R_0402]  190.74 139.22 90 bottom
RM18  2.2_0402_1%  [R_0402]  224.28 125.03 0 bottom
RM19  4.7K_0402_5%  [R_0402]  225.19 111.62 90 bottom
RM20  1K_0402_1%  [R_0402]  220.46 112.05 0 bottom
RM21  1K_0402_1%  [R_0402]  224.31 111.62 90 bottom
RM22  0_0402_5%  [R0402_0OHM]  223.45 111.62 90 bottom
RM23  1K_0402_1%  [R_0402]  165.08 135.18 180 top
RM24  0_0402_5%  [R0402_0OHM]  222.58 111.62 90 bottom
RM25  475_0402_1%  [R_0402]  223.4 124.14 270 bottom
RM26  1K_0402_1%  [R_0402]  164.01 133.83 180 top
RM27  33_0402_1%  [R_0402]  220.66 124.14 270 bottom
RM28  33_0402_1%  [R_0402]  219.78 124.14 270 bottom
RM29  49.9_0402_1%  [R_0402]  218.89 124.14 270 bottom
RM30  2.2K_0402_5%  [R_0402]  217.22 117.63 0 bottom
RM31  100K_0402_5%  [R_0402]  173.79 26.46 90 top
RM32  0_0402_5%  [R0402_0OHM]  173.89 23.52 270 top
RM33  0_0402_5%  [R0402_0OHM]  173 23.52 270 top
RM34  10K_0402_5%  [R_0402]  156.01 15.41 0 bottom
RM35  2.2K_0402_5%  [R_0402]  217.22 118.58 0 bottom
RM36  0_0402_5%  [R0402_0OHM]  215.44 118.58 0 bottom
RM37  0_0402_5%  [R0402_0OHM]  215.44 117.63 0 bottom
RM38  49.9_0402_1%  [R_0402]  221.55 124.14 270 bottom
RM39  0_0402_5%  [R_0402]  164.04 38.06 270 bottom
RM40  0_0402_5%  [R_0402]  163.02 38.06 270 bottom
RM41  100K_0402_5%  [R_0402]  161.3 139.96 0 bottom
RM42  470K_0402_5%  [R_0402]  164.26 139.94 0 bottom
RM45  0_0402_5%  [R_0402]  307.08 16.33 0 top
RM46  0_0402_5%  [R_0402]  307.08 15.36 0 top
RM61  20K_0402_5%  [R_0402]  164.02 130.67 180 bottom
RM62  1K_0402_1%  [R_0402]  163.5 129.29 180 top
RM63  1K_0402_1%  [R_0402]  166.26 131.59 180 bottom
RM64  1K_0402_1%  [R_0402]  163.22 135.18 0 bottom
RM65  1K_0402_1%  [R_0402]  165.33 130.67 0 bottom
RM66  1K_0402_1%  [R_0402]  163.22 133.76 0 bottom
RM67  0_0402_5%~D  [R_0402]  168.29 133.01 180 bottom
RM68  0_0402_5%~D  [R_0402]  168.29 133.9 180 bottom
RM69  20K_0402_1%~D  [R_0402]  154.76 136.08 0 top
RM70  1K_0402_1%  [R_0402]  152.2 127.89 0 bottom
RM71  1K_0402_1%  [R_0402]  154.76 135.14 0 top
RM72  10K_0402_5%  [R_0402]  152.08 137.72 270 bottom
RM73  4.99K_0402_1%  [R_0402]  152.55 136.86 90 top
RM74  1K_0402_1%  [R_0402]  150.67 136.86 90 top
RM75  1K_0402_1%  [R_0402]  163.84 130.7 180 top
RM76  1K_0402_1%  [R_0402]  152.2 127 0 bottom
RM77  4.99K_0402_1%  [R_0402]  152.55 135.85 270 top
RM78  1K_0402_1%  [R_0402]  151.63 137.77 270 top
RM79  1K_0402_1%  [R_0402]  163.84 131.6 180 top
RM81  1K_0402_1%  [R_0402]  150.95 127 180 bottom
RM82  1K_0402_1%  [R_0402]  160.81 133.83 0 top
RM83  1K_0402_1%  [R_0402]  165.47 133.01 0 bottom
RM84  1K_0402_1%  [R_0402]  150.95 127.89 180 bottom
RM85  1K_0402_1%  [R_0402]  163.26 135.16 180 top
RM86  1K_0402_1%  [R_0402]  160.99 129.31 90 top
RM87  10K_0402_5%  [R_0402]  151.17 136.81 90 bottom
RM88  1K_0402_1%  [R_0402]  165.47 133.9 0 bottom
RM89  0_0402_5%  [R_0402]  194.91 133.74 180 top
RM90  0_0402_5%  [R_0402]  194.91 134.7 180 top
RM91  549_0402_1%  [R_0402]  290.39 36.02 0 top
RM92  100K_0402_5%~D  [R_0402]  293.44 30.88 270 top
RM93  100_0402_1%  [R_0402]  296.12 36.06 180 top
RM94  100K_0402_5%~D  [R_0402]  294.65 30.88 270 top
RN5  10K_0402_5%~D  [R_0402]  172.67 19.92 0 top
RN6  4.7K_0402_5%  [R_0402]  163.82 20.78 90 top
RN7  4.7K_0402_5%  [R_0402]  156.97 12.55 270 top
RN8  0_0402_5%  [R_0402]  158.43 21.69 270 top
RN9  0_0402_5%  [R_0402]  164.15 11.64 90 top
RN10  0_0402_5%  [R_0402]  160.21 21.69 270 top
RN11  0_0402_5%  [R_0402]  161.1 21.69 270 top
RN12  0_0402_5%  [R_0402]  162.93 21.69 270 top
RN13  0_0402_5%  [R_0402]  159.7 11.64 90 top
RN14  0_0402_5%  [R_0402]  163.26 11.64 90 top
RN15  0_0402_5%  [R_0402]  160.59 11.64 90 top
RN16  0_0402_5%  [R_0402]  161.48 11.64 90 top
RN17  7.87K_0402_5%  [R_0402]  164.71 20.78 90 top
RN18  4.7K_0402_5%  [R_0402]  157.86 12.55 270 top
RN19  0_0402_5%  [R_0402]  161.99 20.78 90 top
RN20  0_0402_5%  [R_0402]  158.75 12.55 270 top
RN21  0_0402_5%  [R_0402]  162.37 12.55 270 top
RN22  2K_0402_5%  [R_0402]  159.32 20.78 90 top
RN23  5.1K_0402_1%  [R_0402]  165.04 12.55 270 top
RN24  100K_0402_5%~D  [R_0402]  153.28 17.3 0 bottom
RN25  100K_0402_5%  [R_0402]  169.48 32.73 90 top
RN26  100K_0402_5%  [R_0402]  169.48 28.73 90 top
RN27  100K_0402_5%  [R_0402]  164.76 31.75 270 top
RN28  10K_0402_5%  [R_0402]  236.4 8.61 0 top
RN29  10K_0402_5%  [R_0402]  213.41 8.47 0 top
RN30  10K_0402_5%  [R_0402]  214.33 9.36 180 top
RN31  10K_0402_5%  [R_0402]  234.63 8.61 0 top
RN32  10K_0402_5%  [R_0402]  178.14 10.59 0 top
RN33  10K_0402_5%  [R_0402]  165.72 6.06 0 top
RN34  10K_0402_5%  [R_0402]  178.14 12.13 0 top
RN35  10K_0402_5%  [R_0402]  166.64 6.95 180 top
RP2  33_0804_8P4R_5%  [RP_0804_8P4R]  236.8 40.4 180 bottom
RPH1  10K_0804_8P4R_5%~D  [RP_0804_8P4R]  208.48 39.17 180 top
RPH2  10K_0804_8P4R_5%~D  [RP_0804_8P4R]  232.22 44.85 0 top
RPH3  10K_0804_8P4R_5%  [RP_0804_8P4R]  232.22 48.78 0 top
RPH4  2.2K_0804_8P4R_5%  [RP_0804_8P4R]  228.02 24.73 270 top
RPH5  15_0804_8P4R_5%  [RP_0804_8P4R]  218.56 18.31 90 bottom
RPH6  10K_0804_8P4R_5%  [RP_0804_8P4R]  226.52 24.73 270 bottom
RPH7  10K_0804_8P4R_5%  [RP_0804_8P4R]  221.54 25.14 270 top
RR1  33_0402_1%  [R_0402]  329.25 24.12 270 top
RR2  6.2K_0402_1%  [R_0402]  331.99 14.57 180 top
RR3  33_0402_1%  [R_0402]  325.49 24.11 270 top
RR4  10K_8P4R_5%  [RP_0804_8P4R]  321.45 18.39 0 top
RR5  0_0402_5%  [R_0402]  327.37 23.19 90 top
RR6  0_0402_5%  [R_0402]  326.45 23.19 90 top
RR7  0_0402_5%  [R_0402]  331.41 21.52 0 top
RR8  0_0402_5%  [R_0402]  331.42 22.49 0 top
RR9  22_0402_5%~D  [R_0402]  299.3 20.41 90 bottom
RR10  22_0402_5%~D  [R_0402]  299.3 34.46 270 bottom
RT4  0_0603_5%  [R_0603]  198.08 134.06 270 bottom
RT5  0_0603_5%  [R0603_0OHM]  199.19 130.27 180 bottom
RT6  0_0603_5%  [R0603_0OHM]  197.79 131.49 180 bottom
RT11  10K_0402_5%  [R_0402]  193.18 134.11 180 bottom
RT12  33_0402_5%  [R_0402]  217.69 26.38 90 top
RT13  33_0402_5%  [R_0402]  218.63 28.4 180 top
RT14  33_0402_5%  [R_0402]  213.13 26.58 270 top
RT15  0_0402_5%  [R_0402]  239.77 36.54 0 bottom
RT16  33_0402_5%  [R_0402]  239.77 35.09 0 bottom
RU4  100K_0402_5%  [R_0402]  14.91 32.86 180 top
RU5  220K_0402_5%  [R_0402]  16.65 39.91 180 bottom
RU6  1M_0402_5%  [R_0402]  17.45 36.98 180 top
RV1  10K_0402_5%  [R_0402]  90.21 119.2 315 top
RV2  10K_0402_5%  [R_0402]  89.61 129.34 225 bottom
RV3  0_0402_5%  [R0402_0OHM]  85.48 117.88 135 bottom
RV6  0_0402_5%  [R_0402]  98.72 125.3 135 top
RV7  0_0402_5%  [R_0402]  98 124.59 135 top
RV8  100K_0402_5%  [R_0402]  90.86 119.87 315 top
RV9  100K_0402_5%  [R_0402]  85.29 113.88 135 top
RV12  100K_0402_5%  [R_0402]  83.07 114.71 180 top
RV13  0_0402_5%  [R_0402]  84.41 126.14 180 bottom
RV14  0_0402_5%  [R_0402]  98.81 126.86 315 top
RV15  100K_0402_5%  [R_0402]  144.77 136.92 270 bottom
RV16  100K_0402_5%  [R_0402]  143.89 136.92 270 bottom
RV17  1M_0402_5%  [R_0402]  140.12 136.96 270 bottom
RV18  5.1M_0402_5%  [R_0402]  141.01 136.04 90 bottom
RV19  0_0402_5%~D  [R_0402]  122.8 134.21 45 bottom
RV20  10K_0402_5%  [R_0402]  129.31 134.76 90 bottom
RV21  0_0402_5%~D  [R_0402]  122.08 134.92 45 bottom
RV22  0_0402_5%~D  [R_0402]  126.12 134.27 45 bottom
RV24  0_0402_5%~D  [R_0402]  125.4 134.99 45 bottom
RV26  0_0402_5%~D  [R_0402]  119.82 134.44 45 bottom
RV28  0_0402_5%~D  [R_0402]  119.1 135.15 45 bottom
RV29  0_0402_5%~D  [R_0402]  115.96 135.33 45 bottom
RV30  0_0402_5%~D  [R_0402]  116.67 134.61 45 bottom
RV31  2.2K_0402_5%  [R_0402]  112.82 137.47 180 bottom
RV32  2.2K_0402_5%  [R_0402]  112.82 138.36 180 bottom
RV35  10K_0402_1%  [R_0402]  154.57 62.85 180 top
RV36  0_0402_5%  [R0402_0OHM]  99.53 127.53 315 top
RV37  10K_0402_5%  [R_0402]  145.04 83.19 180 bottom
RV38  100K_0402_5%~D  [R_0402]  169.05 70.39 90 top
RV39  10K_0402_5%  [R_0402]  152.57 67.16 0 bottom
RV40  0_0402_5%  [R_0402]  155.2 67.07 90 bottom
RV41  20K_0402_1%~D  [R_0402]  110.5 137.34 270 bottom
RV42  2.2K_0402_5%  [R_0402]  113.2 143.66 180 bottom
RV45  10K_0402_5%  [R_0402]  82.15 122.19 225 bottom
RV46  0_0402_5%  [R0402_0OHM]  96.39 130.78 315 bottom
RV47  0_0603_5%  [R0603_0OHM]  92.46 124.71 45 bottom
RV49  10K_0402_5%  [R_0402]  156.34 66.84 180 top
RV50  10K_0402_5%  [R_0402]  154.57 63.74 180 top
RV51  10K_0402_5%  [R_0402]  156.35 65.88 180 top
RV52  10M_0402_5%  [R_0402]  168.65 65.25 0 bottom
RV53  10K_0402_5%  [R_0402]  153.49 70.94 180 top
RV54  200_0402_1%  [R_0402]  167.83 97.36 90 top
RV55  10K_0402_1%  [R_0402]  157.2 62.12 180 bottom
RV56  10K_0402_5%  [R_0402]  144.95 78.2 90 bottom
RV57  2.49K_0402_1%  [R_0402]  155.45 100.14 0 top
RV58  10K_0402_5%  [R_0402]  156.67 76.06 180 bottom
RV59  10K_0402_5%  [R_0402]  155.2 69.38 90 bottom
RV61  100K_0402_5%~D  [R_0402]  152.58 68.19 0 top
RV62  10K_0402_5%  [R_0402]  144.93 75.99 90 bottom
RV63  10K_0402_5%  [R_0402]  154.57 65.88 180 top
RV64  10K_0402_5%  [R_0402]  153.49 71.85 180 bottom
RV66  40.2K_0402_1%  [R_0402]  154.99 72.32 0 top
RV67  10K_0402_5%  [R_0402]  167.81 84.09 270 top
RV68  10K_0402_5%  [R_0402]  154.82 78.62 0 top
RV69  10K_0402_5%  [R_0402]  155.84 81.51 180 top
RV77  40.2_0402_1%  [R_0402]  187.68 99.04 0 top
RV78  40.2_0402_1%  [R_0402]  188.16 109.66 270 bottom
RV79  60.4_0402_1%  [R_0402]  187.27 109.66 270 bottom
RV81  0_0402_5%  [R0402_0OHM]  91.22 130.83 315 bottom
RV93  0_0402_5%~D  [R_0402]  140.07 80.01 0 bottom
RV107  10K_0402_5%  [R_0402]  166.2 110.92 180 bottom
RV108  10K_0402_5%  [R_0402]  185.17 109.74 90 bottom
RV109  10K_0402_5%  [R_0402]  166.06 109.53 270 bottom
RV110  10K_0402_5%  [R_0402]  186.34 110.66 270 bottom
RV111  10K_0402_5%  [R_0402]  202.7 91.22 90 bottom
RV112  10K_0402_5%  [R_0402]  190.3 109.24 180 bottom
RV113  10K_0402_5%  [R_0402]  193.82 109.25 180 bottom
RV114  10K_0402_5%  [R_0402]  203.65 92.2 270 bottom
RV115  10K_0402_5%  [R_0402]  209.35 82.95 0 top
RV116  1K_0402_1%  [R_0402]  179.64 120.44 270 top
RV117  1K_0402_1%  [R_0402]  162.45 120.55 90 bottom
RV118  1K_0402_1%  [R_0402]  171.19 130.6 0 top
RV119  1K_0402_1%  [R_0402]  169.42 130.6 180 bottom
RV120  121_0402_1%  [R_0402]  162.37 119.52 90 top
RV121  121_0402_1%  [R_0402]  179.59 120.96 270 bottom
RV123  80.6_0402_1%  [R_0402]  162.37 121.62 90 top
RV125  100K_0402_5%~D  [R_0402]  141.91 83.19 0 bottom
RV131  1K_0402_1%  [R_0402]  180.47 120.96 270 bottom
RV132  1K_0402_1%  [R_0402]  180.53 120.44 270 top
RV133  1K_0402_1%  [R_0402]  188.89 130.63 90 bottom
RV134  1K_0402_1%  [R_0402]  189.86 130.68 0 top
RV135  121_0402_1%  [R_0402]  197.61 121.43 90 bottom
RV136  121_0402_1%  [R_0402]  198.11 126.77 0 top
RV138  80.6_0402_1%  [R_0402]  197.61 120.12 270 bottom
RV140  1K_0402_1%  [R_0402]  229.45 92.1 0 bottom
RV141  80.6_0402_1%  [R_0402]  218.41 101.44 0 top
RV142  549_0402_1%  [R_0402]  213.89 101.61 180 bottom
RV143  549_0402_1%  [R_0402]  214.75 101.61 0 bottom
RV144  931_0402_1%  [R_0402]  213.89 102.5 180 bottom
RV145  1.33K_0402_1%  [R_0402]  216.53 102.51 0 bottom
RV146  10K_0402_5%  [R_0402]  210.36 85.68 90 bottom
RV147  10K_0402_5%  [R_0402]  211.71 84.23 0 bottom
RV148  10K_0402_5%  [R_0402]  210.27 83.98 180 top
RV149  10K_0402_5%  [R_0402]  210.25 70.06 90 top
RV150  10K_0402_5%  [R_0402]  211.34 64.94 90 top
RV151  10K_0402_5%  [R_0402]  213.69 65.78 270 top
RV152  10K_0402_5%  [R_0402]  209.74 68.94 270 top
RV153  10K_0402_5%  [R_0402]  156.36 101.51 180 top
RV156  121_0402_1%  [R_0402]  219.33 101.49 90 bottom
RV158  1.33K_0402_1%  [R_0402]  229.54 96.37 90 bottom
RV159  1K_0402_1%  [R_0402]  229.45 91.2 0 bottom
RV160  121_0402_1%  [R_0402]  220.29 101.44 90 top
RV161  1K_0402_1%  [R_0402]  218.65 84.18 180 bottom
RV164  931_0402_1%  [R_0402]  214.75 102.51 0 bottom
RV165  1K_0402_1%  [R_0402]  223.96 83.3 0 top
RV166  121_0402_1%  [R_0402]  218.65 83.3 180 bottom
RV167  10K_0402_5%  [R_0402]  149.28 73.37 0 bottom
RV168  33_0402_5%~D  [R_0402]  152.85 73.5 90 bottom
RV169  33_0402_5%~D  [R_0402]  152.9 77.01 0 bottom
RV170  33_0402_5%~D  [R_0402]  152.9 76.13 0 bottom
RV171  121_0402_1%  [R_0402]  219.03 83.28 180 top
RV172  1K_0402_1%  [R_0402]  220.86 66.21 270 bottom
RV175  80.6_0402_1%  [R_0402]  179.58 121.36 90 top
RV178  80.6_0402_1%  [R_0402]  197.61 120.98 90 top
RV179  80.6_0402_1%  [R_0402]  220.28 101.46 0 bottom
RV182  80.6_0402_1%  [R_0402]  219.7 83.21 0 bottom
RV185  1K_0402_1%  [R_0402]  229.44 74.03 0 bottom
RV187  10K_0402_5%  [R_0402]  158.13 73.74 270 bottom
RV188  1K_0402_1%  [R_0402]  229.45 74.97 0 bottom
RV189  549_0402_1%  [R_0402]  161.71 131.99 180 top
RV190  1.33K_0402_1%  [R_0402]  168.55 130.6 180 top
RV191  1.8K_0402_5%  [R_0402]  165.88 51.81 0 top
RV192  1.8K_0402_5%  [R_0402]  164.66 54.27 180 top
RV193  931_0402_1%  [R_0402]  160.07 129.16 270 top
RV194  931_0402_1%  [R_0402]  159.12 129.96 90 top
RV195  549_0402_1%  [R_0402]  162.14 126.33 90 top
RV196  1.33K_0402_1%  [R_0402]  159.12 131.76 90 top
RV197  549_0402_1%  [R_0402]  200.36 127.68 180 top
RV198  1.33K_0402_1%  [R_0402]  194.33 130.68 180 top
RV199  931_0402_1%  [R_0402]  199.46 129.56 0 top
RV200  931_0402_1%  [R_0402]  200.36 128.57 180 top
RV201  549_0402_1%  [R_0402]  202.21 129.56 180 top
RV202  1.33K_0402_1%  [R_0402]  198.57 127.67 90 top
RV203  549_0402_1%  [R_0402]  217.29 66.21 0 bottom
RV204  1K_0402_1%  [R_0402]  221.03 66.16 270 top
RV205  931_0402_1%  [R_0402]  217.29 64.44 0 bottom
RV206  931_0402_1%  [R_0402]  217.29 65.33 0 bottom
RV207  549_0402_1%  [R_0402]  217.29 63.55 0 bottom
RV208  0_0402_5%~D  [R_0402]  155.27 56.44 90 bottom
RV209  1.33K_0402_1%  [R_0402]  219.07 65.33 0 bottom
RV212  80.6_0402_1%  [R_0402]  220.97 83.28 0 top
RV213  1.33K_0402_1%  [R_0402]  219.07 63.55 0 bottom
RV214  15K_0402_1%  [R_0402]  153.49 77.69 180 top
RV215  15K_0402_1%  [R_0402]  155.91 70.41 180 top
RV216  4.99K_0402_1%  [R_0402]  156.39 76.05 180 top
RV217  4.99K_0402_1%  [R_0402]  153.49 73.7 180 top
RV218  34.8K_0402_1%  [R_0402]  153.49 76.8 180 top
RV219  20K_0402_1%  [R_0402]  153.49 71.85 180 top
RV221  4.99K_0402_1%  [R_0402]  156.4 76.99 180 top
RV223  4.99K_0402_1%  [R_0402]  155.91 69.22 180 top
RV224  45.3K_0402_1%  [R_0402]  155.91 71.36 180 top
RV226  4.99K_0402_1%  [R_0402]  155.89 68.01 180 top
RV228  45.3K_0402_1%  [R_0402]  155.91 73.27 180 top
RV229  4.99K_0402_1%  [R_0402]  153.49 70.03 180 top
RV230  49.9K_0402_1%  [R_0402]  153.49 72.8 180 top
RV231  4.99K_0402_1%  [R_0402]  153.49 69.1 180 top
RV232  15K_0402_1%  [R_0402]  155.91 74.22 180 top
RV233  24.9K_0402_1%  [R_0402]  154.57 66.84 180 top
RV241  10K_0402_1%  [R_0402]  156.58 39.7 0 top
RV242  10K_0402_1%  [R_0402]  156.52 35.33 0 top
RV243  10K_0402_1%  [R_0402]  156.52 34.44 0 top
RV293  4.99K_0402_1%  [R_0402]  103.49 138.18 0 bottom
RV294  4.7K_0402_5%  [R_0402]  112.79 140.15 270 bottom
RV295  4.7K_0402_5%  [R_0402]  111.91 139.23 90 bottom
RV296  4.7K_0402_5%  [R_0402]  104.41 140.03 180 bottom
RV297  4.7K_0402_5%  [R_0402]  102 140.03 180 bottom
RV298  4.7K_0402_5%  [R_0402]  104.41 139.05 180 bottom
RV299  4.7K_0402_5%  [R_0402]  102.01 139.11 180 bottom
RV300  4.7K_0402_5%  [R_0402]  104.41 140.97 180 bottom
RV301  4.7K_0402_5%  [R_0402]  102 140.97 180 bottom
RV302  4.7K_0402_5%  [R_0402]  109.62 137.34 270 bottom
